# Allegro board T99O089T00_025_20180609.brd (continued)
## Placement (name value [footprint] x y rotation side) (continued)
C1405  22uF  [C-0805]  109.73 117.91 0 bottom
C1406  1UF  [S-C-0402]  118.36 129.72 270 bottom
C1407  0.1uF  [S-C-0402]  117.32 123.7 0 bottom
C1408  1UF  [S-C-0402]  111.25 118.17 180 bottom
C1409  0.1uF  [S-C-0402]  113.17 133.68 90 bottom
C1410  100nF  [C-0402S0]  29.47 45.23 90 bottom
C1411  1UF  [C-0402S0]  116.81 197.8 180 bottom
C1412  1UF  [C-0402S0]  75.82 122.34 270 bottom
C1413  1UF  [C-0402S0]  129.2 101.67 90 bottom
C1414  1nF  [C-0402S0]  118.59 186.62 0 top
C1415  1nF  [C-0402S0]  117.32 186.62 0 top
C1416  1nF  [C-0402S0]  116.05 186.62 0 top
C1417  1nF  [C-0402S0]  66.17 127.38 0 bottom
C1418  1nF  [C-0402S0]  114.78 186.62 0 top
C1419  1nF  [C-0402S0]  81.28 192.28 180 top
C1420  1nF  [C-0402S0]  110.33 194.24 270 top
C1421  1nF  [C-0402S0]  121.13 186.62 0 top
C1422  1nF  [C-0402S0]  119.86 186.62 0 top
C1548  1UF  [C-0402S0]  95 181.91 0 top
C1549  1uF  [C-0603S0]  261.97 188.4 270 top
C1550  22uF  [C-1210]  306.62 190.36 0 top
C1551  1uF  [C-0603S0]  260.91 189.11 0 bottom
C1552  1uF  [C-0603S0]  262.1 183.06 90 bottom
C1553  10uF  [C-0603S0]  286 190.68 0 bottom
C1554  100nF  [C-0402S0]  286.13 193.68 180 bottom
C1555  22nF  [C-0402S0]  259.02 190.09 270 bottom
C1556  1uF  [C-0603S0]  305.69 185.24 180 top
C1557  22uF  [C-1210]  57.12 163.66 0 top
C1558  100nF  [C-0402S0]  56.95 159.41 180 top
C1560  1uF  [C-0603S0]  276.84 188.92 90 bottom
C1561  1uF  [C-0603S0]  277.72 188.41 270 top
C1562  1uF  [C-0603S0]  277.85 183.08 90 bottom
C1563  1uF  [C-0603S0]  265.86 188.52 90 bottom
C1564  1uF  [C-0603S0]  266.8 188.52 270 top
C1565  1uF  [C-0603S0]  267.05 182.81 90 bottom
C1566  22nF  [C-0402S0]  276.68 190.14 90 bottom
C1567  22nF  [C-0402S0]  264.01 188.91 180 bottom
C1576  1uF  [C-0603S0]  285.16 186.1 90 bottom
C1577  1uF  [C-0603S0]  270.86 188.8 0 bottom
C1578  1uF  [C-0603S0]  269.09 185.04 180 top
C1579  1uF  [C-0603S0]  273.15 183.06 90 bottom
C1580  1uF  [C-0603S0]  280.25 186.31 0 bottom
C1581  1uF  [C-0603S0]  280.88 188.34 270 top
C1582  22nF  [C-0402S0]  269.47 189.08 0 bottom
C1583  22nF  [C-0402S0]  281.18 188.16 90 bottom
C1592  220pF  [C-0402S0]  43.43 200.28 180 top
C1593  220pF  [C-0402S0]  33.27 206.5 0 bottom
C1594  220pF  [C-0402S0]  36.96 197.74 90 bottom
C1595  10pF  [C-0402S0]  54.64 195.91 270 top
C1596  220pF  [C-0402S0]  45.95 191.57 0 bottom
C1597  220pF  [C-0402S0]  37.97 196.22 180 bottom
C1598  220pF  [C-0402S0]  43.43 196.09 180 top
C1599  220pF  [C-0402S0]  36.96 200.91 90 bottom
C1600  220pF  [C-0402S0]  37.08 204.98 180 bottom
C1601  10pF  [C-0402S0]  54.63 202.06 270 top
C1602  220pF  [C-0402S0]  45.59 191.9 0 top
C1603  220pF  [C-0402S0]  37.97 193.68 0 bottom
C1604  100nF  [C-0402S0]  69.34 178.69 0 bottom
C1622  27pF  [C-0402S0]  87.38 87.41 0 top
C1623  27pF  [C-0402S0]  87.38 89.49 180 top
C1624  47uF  [C-0805-H1_35]  100.2 86.83 0 bottom
C1625  1UF  [C-0402S0]  95.02 88.93 270 bottom
C1626  1UF  [C-0402S0]  94.55 92.31 270 bottom
C1627  1UF  [C-0402S0]  97.66 86.67 180 bottom
C1628  0.1uF  [C-0402S0]  92.76 94.4 90 bottom
C1629  0.1uF  [C-0402S0]  100.84 92.77 180 bottom
C1630  0.1uF  [C-0402S0]  98.68 86.67 0 bottom
C1631  0.1uF  [C-0402S0]  95.02 89.91 90 bottom
C1632  1uF  [C-0603S0]  101.6 84.01 90 top
C1633  1uF  [C-0603S0]  93.29 91.07 270 bottom
C1634  1uF  [C-0603S0]  97.43 93.26 180 bottom
C1635  0.1uF  [C-0402S0]  69.16 174.14 0 top
C1636  10uF  [C-0603S0]  4.47 103.33 180 top
C1637  39nF  [C-0402S0]  88.9 90.23 270 top
C1638  10uF  [C-0603S0]  95.38 86.54 0 bottom
C1639  1UF  [C-0402S0]  96.65 86.67 180 bottom
C1640  1UF  [C-0402S0]  92.38 87.61 270 bottom
C1641  100nF  [C-0402S0]  34.49 49.26 270 bottom
C1642  1UF  [C-0402S0]  93.85 86.03 180 bottom
C1643  10uF  [C-0603S0]  92.58 85.27 0 bottom
C1644  1UF  [C-0402S0]  125.38 118.53 180 top
C1672  1nF  [C-0402S0]  66.42 39.37 0 top
C1673  1nF  [C-0402S0]  80.79 43.88 180 bottom
C1674  1nF  [C-0402S0]  83.84 43.87 180 bottom
C1678  1UF  [C-0402S0]  47.35 89.48 90 bottom
C1679  100nF  [C-0402S0]  72.1 55.51 0 bottom
C1680  10pF  [C-0402S0]  62.73 41.33 0 top
C1681  10pF  [C-0402S0]  59.69 41.33 0 top
C1682  100nF  [C-0402S0]  71.63 52.7 90 bottom
C1683  100nF  [C-0402S0]  71.63 53.97 90 bottom
C1684  100nF  [C-0402S0]  76.45 52.33 90 bottom
C1685  150uF/ 3.22A  [CAH-R8-H6_9S0]  62.03 47.2 90 top
C1686  1UF  [C-0402S0]  56.86 45.44 180 bottom
C1687  1UF  [C-0402S0]  130.67 116.58 90 top
C1688  10uF  [C-0603S0]  126.92 116.27 0 top
C1689  1UF  [C-0402S0]  89.84 85.02 0 bottom
C1690  0.1uF  [C-0402S0]  134.81 121.33 270 top
C1815  1UF  [C-0402S0]  8.3 17.59 270 top
C1816  10uF  [C-0603S0]  5.44 102.36 180 bottom
C1817  1UF  [C-0402S0]  46.3 82.83 0 bottom
C1818  1UF  [C-0402S0]  73.81 63.07 0 bottom
C1935  1UF  [C-0402S0]  24.72 63.16 90 top
C1938  1UF  [C-0402S0]  20.82 20.23 270 top
C1940  1UF  [S-C-0402]  112.34 83.17 180 bottom
C1941  10uF  [S-C-0402]  113.38 83.19 0 bottom
C1942  1UF  [S-C-0402]  116.77 132.08 270 bottom
C1956  10uF  [C-0603S0]  8.3 27.13 90 bottom
C1978  0.1uF  [C-0402S0]  10.48 32.13 90 bottom
C1979  100nF  [C-0402S0]  35.43 46.34 270 bottom
C1980  100nF  [C-0402S0]  27.41 49.36 270 bottom
C1981  100nF  [C-0402S0]  50.42 66.04 0 top
C1982  10uF  [C-0603S0]  9.54 42.62 180 bottom
C1983  10uF  [C-0603S0]  13 42.62 0 bottom
C1985  0.1uF  [C-0402S0]  17.42 41.23 270 bottom
C1986  0.1uF  [C-0402S0]  17.42 39.96 270 bottom
C1987  0.1uF  [C-0402S0]  6.35 29.57 180 bottom
C1988  10uF  [C-0603S0]  8.3 29.98 270 bottom
C1989  1nF  [S-C-0402]  6.35 31.31 0 bottom
C1990  0ohm  [C-0402S0]  4.32 27.87 0 bottom
C1991  10uF  [C-0603S0]  74.67 77.48 0 bottom
C1992  0.1uF  [S-C-0402]  75.74 73.41 90 bottom
C1993  0.1uF  [S-C-0402]  80.31 80.39 180 bottom
C1994  0.1uF  [S-C-0402]  70.28 73.41 270 bottom
C1995  0.1uF  [S-C-0402]  72.06 73.41 270 bottom
C1996  10uF  [C-0603S0]  72.05 85.99 180 bottom
C1997  0.1uF  [S-C-0402]  73.39 86.17 180 bottom
C1998  0.1uF  [S-C-0402]  68.5 73.46 270 bottom
C1999  0.1uF  [S-C-0402]  73.36 77.3 0 bottom
C2000  0.1uF  [S-C-0402]  72.26 88.58 270 bottom
C2001  0.1uF  [S-C-0402]  80.37 83.21 0 bottom
C2002  0.1uF  [C-0402S0]  51.51 191.78 180 top
C2038  100nF  [C-0402S0]  142.26 130.82 0 top
C2039  10uF  [C-0603S0]  143.78 116.64 180 bottom
C2040  100nF  [C-0402S0]  138.22 122.48 90 bottom
C2041  100nF  [C-0402S0]  140.33 119.56 0 bottom
C2042  1UF  [C-0402S0]  11.18 77.47 270 top
C2043  10uF  [C-0603S0]  178.89 156.71 90 top
C2044  1UF  [C-0402S0]  179.17 155.49 270 top
C2045  100nF  [C-0402S0]  133.98 117.66 180 bottom
C2046  10uF  [C-0603S0]  134.62 120.71 90 bottom
C2047  100nF  [C-0402S0]  137.54 120.71 270 bottom
C2048  1UF  [C-0402S0]  150.06 141.73 90 top
C2049  10uF  [C-0603S0]  187.63 156.89 90 bottom
C2050  1UF  [C-0402S0]  187.32 155.61 270 bottom
C2051  1UF  [C-0402S0]  160.78 83.47 180 top
C2052  10uF  [C-0603S0]  163.83 83.22 180 top
C2053  1UF  [C-0402S0]  165.1 83.42 0 top
C2054  1UF  [C-0402S0]  152.49 113.67 180 top
C2055  10uF  [C-0603S0]  155.2 113.82 180 top
C2056  1UF  [C-0402S0]  156.51 113.92 0 top
C2057  1UF  [C-0402S0]  168.16 97.72 0 top
C2058  10uF  [C-0603S0]  165.24 97.59 0 top
C2059  1UF  [C-0402S0]  163.97 97.46 180 top
C2060  10uF  [C-1206]  303.28 190.57 0 top
C2061  100nF  [C-0402S0]  92.48 194.78 270 bottom
C2062  100nF  [C-0402S0]  67.82 183.9 0 bottom
C2063  0.1uF  [S-C-0402]  90.04 167.26 180 bottom
C2064  0.1uF  [S-C-0402]  91.06 167.26 180 bottom
C2065  0.1uF  [S-C-0402]  93.22 167.26 180 bottom
C2066  0.1uF  [S-C-0402]  94.23 167.26 180 bottom
C2067  0.1uF  [S-C-0402]  107.54 167.24 180 bottom
C2068  0.1uF  [S-C-0402]  108.56 167.24 180 bottom
C2069  0.1uF  [S-C-0402]  119.13 147.96 0 bottom
C2070  0.1uF  [S-C-0402]  118.11 147.96 0 bottom
C2071  0.1uF  [S-C-0402]  124.43 148.01 0 bottom
C2072  0.1uF  [S-C-0402]  125.57 148.01 0 bottom
C2073  0.1uF  [S-C-0402]  128.02 148.01 0 bottom
C2074  0.1uF  [S-C-0402]  127 148.01 0 bottom
C2076  1UF  [C-0402S0]  57.36 52.43 270 bottom
C2077  0.1uF  [S-C-0402]  276.6 94.39 180 bottom
C2078  22uF  [C-0805]  25.52 104.09 0 top
C2079  10uF  [C-0603S0]  23.75 104.01 0 top
C2080  1nF  [S-C-0402]  20.43 91.8 90 bottom
C2081  0.1uF  [S-C-0402]  19.93 90.3 0 bottom
C2082  0.1uF  [S-C-0402]  22.93 94.3 0 bottom
C2083  0.1uF  [S-C-0402]  191.99 130.58 0 bottom
C2084  22uF  [C-0805]  4.9 86.38 270 top
C2085  10uF  [C-0603S0]  5.03 88.29 270 top
C2086  1nF  [S-C-0402]  14.43 87.81 90 bottom
C2087  0.1uF  [S-C-0402]  14.43 88.79 270 bottom
C2088  0.1uF  [S-C-0402]  17.43 86.8 270 bottom
C2089  10uF  [C-0603S0]  31.05 103.03 270 bottom
C2090  47uF  [C-1206]  10.84 103.4 0 top
C2091  10uF  [C-0603S0]  13.13 103.35 0 top
C2092  1nF  [S-C-0402]  21.43 95.8 90 bottom
C2093  0.1uF  [S-C-0402]  14.43 91.8 270 bottom
C2094  0.1uF  [S-C-0402]  14.43 90.8 90 bottom
C2095  0.1uF  [S-C-0402]  21.43 94.8 270 bottom
C2096  0.1uF  [S-C-0402]  21.43 93.8 270 bottom
C2097  10uF  [C-0603S0]  88.27 81.34 180 bottom
C2098  47uF  [C-1206]  13.56 102.7 180 bottom
C2099  10uF  [C-0603S0]  15.62 102.37 180 bottom
C2100  0.1uF  [S-C-0402]  15.93 97.3 0 bottom
C2101  1nF  [S-C-0402]  15.43 98.8 90 bottom
C2102  0.1uF  [S-C-0402]  14.43 97.8 270 bottom
C2103  0.1uF  [S-C-0402]  22.93 97.3 0 bottom
C2104  0.1uF  [S-C-0402]  21.93 97.3 0 bottom
C2105  10uF  [C-0603S0]  75.46 47.45 180 top
C2106  47uF  [C-1206]  29.04 99.63 180 bottom
C2107  10uF  [C-0603S0]  27.11 99.68 180 bottom
C2108  0.1uF  [S-C-0402]  17.93 96.3 0 bottom
C2109  1nF  [S-C-0402]  20.93 97.3 0 bottom
C2110  0.1uF  [S-C-0402]  20.93 90.3 180 bottom
C2111  0.1uF  [S-C-0402]  22.43 91.8 270 bottom
C2112  0.1uF  [S-C-0402]  23.93 94.3 180 bottom
C2113  10uF  [C-0603S0]  101.6 82.61 270 top
C2114  47uF  [C-1206]  5.52 92.31 90 top
C2115  10uF  [C-0603S0]  5.33 90.38 90 top
C2116  0.1uF  [S-C-0402]  24.43 91.8 270 bottom
C2117  1nF  [S-C-0402]  13.43 95.8 90 bottom
C2118  0.1uF  [S-C-0402]  24.93 94.3 0 bottom
C2119  0.1uF  [S-C-0402]  24.93 97.3 180 bottom
C2120  0.1uF  [S-C-0402]  15.43 95.8 90 bottom
C2121  0.1uF  [C-0402S0]  101.22 90.99 0 bottom
C2122  100nF  [C-0402S0]  68.2 177.93 0 bottom
C2123  100nF  [C-0402S0]  93.98 178.87 270 top
C2124  100nF  [C-0402S0]  116.05 115.28 0 bottom
C2125  10uF  [S-C-0402]  37.9 56.81 0 top
C2127  10uF  [C-0603S0]  27.05 89.21 90 bottom
C2128  0.1uF  [S-C-0402]  24.43 89.8 270 bottom
C2129  0.1uF  [S-C-0402]  22.43 89.8 270 bottom
C2130  10uF  [C-0603S0]  27.91 90.59 90 bottom
C2131  0.1uF  [S-C-0402]  22.43 90.8 270 bottom
C2132  1UF  [C-0402S0]  162.3 133.79 0 bottom
C2133  10uF  [C-0603S0]  14.71 138.96 0 bottom
C2134  47uF  [C-1206]  25.5 140.04 180 bottom
C2135  10uF  [C-0603S0]  27.43 140.84 180 bottom
C2136  0.1uF  [C-0402S0]  29.66 140.66 180 bottom
C2137  1nF  [C-0402S0]  28.65 140.66 0 bottom
C2138  100uF  [C-1210]  22.26 140.1 180 bottom
C2139  1UF  [S-C-0402]  16.93 96.3 180 bottom
C2140  10uF  [C-0603S0]  161.35 125.11 0 bottom
C2141  1UF  [C-0402S0]  156.72 127.31 90 bottom
C2142  1UF  [C-0402S0]  166.24 125.15 0 bottom
C2143  1UF  [C-0402S0]  160.15 127.56 180 bottom
C2144  1UF  [C-0402S0]  159.13 133.03 180 bottom
C2145  1UF  [C-0402S0]  160.03 131.42 90 bottom
C2146  10uF  [C-0603S0]  162.71 136.05 90 bottom
C2147  1UF  [C-0402S0]  160.15 133.03 0 bottom
C2148  1UF  [C-0402S0]  156.46 133.53 180 bottom
C2149  1UF  [C-0402S0]  158.49 127.04 90 bottom
C2150  1UF  [C-0402S0]  154.91 133.36 180 bottom
C2151  1UF  [C-0402S0]  153.14 129.34 270 bottom
C2152  1UF  [C-0402S0]  154.03 128.15 270 bottom
C2153  10uF  [C-0603S0]  150.39 137.03 90 top
C2154  1UF  [C-0402S0]  180.59 158.3 0 top
C2155  1UF  [C-0402S0]  159.71 130.17 90 bottom
C2156  10uF  [C-0603S0]  163.18 129.34 90 bottom
C2157  1UF  [C-0402S0]  185.68 156.6 180 bottom
C2158  0.1uF  [C-0402S0]  147.68 135.57 270 top
C2159  0.1uF  [C-0402S0]  147.65 134.56 270 top
C2160  100nF  [C-0402S0]  72.39 94.36 90 bottom
C2161  100nF  [C-0402S0]  39.34 189.24 270 bottom
C2162  100nF  [C-0402S0]  25.86 124.92 90 top
C2163  0.1uF  [C-0402S0]  164.57 132.14 270 top
C2164  0.1uF  [C-0402S0]  164.57 131.12 270 top
C2165  0.1uF  [C-0402S0]  164.57 129.09 270 top
C2166  0.1uF  [C-0402S0]  164.57 128.07 270 top
C2167  0.1uF  [C-0402S0]  161.08 122.87 270 top
C2168  0.1uF  [C-0402S0]  161.08 121.85 270 top
C2169  0.1uF  [C-0402S0]  49.86 113.31 90 bottom
C2170  0.1uF  [C-0402S0]  49.86 109.47 90 bottom
C2171  1UF  [C-0402S0]  165.11 140.23 0 bottom
C2172  1UF  [S-C-0402]  24.43 95.8 90 bottom
C2173  22uF  [C-0805]  163.14 125 0 bottom
C2174  22uF  [C-0805]  162.81 137.76 90 bottom
C2175  22uF  [C-0805]  151.38 139.57 0 top
C2176  150uF/ 3.22A  [CAH-R8-H6_9S0]  38.97 185.6 90 top
C2204  0.1uF  [C-0402S0]  296.85 91.75 90 top
C2205  0.1uF  [C-0402S0]  296.85 92.76 90 top
C2206  100nF  [C-0402S0]  105.05 77.7 270 bottom
C2207  10uF  [C-0603S0]  104.78 82.1 270 bottom
C2208  100nF  [C-0402S0]  106.63 82.94 180 bottom
C2209  100nF  [C-0402S0]  97.16 178.87 270 top
C2210  10uF  [C-0603S0]  92.21 191.87 90 bottom
C2211  100nF  [C-0402S0]  90.23 192.28 180 bottom
C2215  100nF  [C-0402S0]  136.86 201.11 90 top
C2216  100nF  [C-0402S0]  153.48 76.53 0 top
C2217  100nF  [C-0402S0]  141.4 76.53 0 top
C2218  1nF  [C-0402S0]  118.87 192.3 0 bottom
C2219  100nF  [S-C-0402]  274.14 11.18 270 bottom
C2220  0.1uF  [C-0402S0]  84.85 43.87 180 bottom
C2221  100nF  [S-C-0402]  217.68 27.76 90 bottom
C2224  1UF  [C-0402S0]  78.5 173.53 270 top
C2229  1UF  [C-0402S0]  73.84 65.72 270 top
C2235  0.1uF  [C-0402S0]  185.67 146.31 180 top
C2236  0.1uF  [C-0402S0]  186.69 146.31 180 top
C2237  0.1uF  [C-0402S0]  188.72 151.69 270 top
C2238  0.1uF  [C-0402S0]  188.72 152.71 270 top
C2239  0.1uF  [C-0402S0]  190.3 120.65 90 top
C2240  0.1uF  [C-0402S0]  43.06 113.46 0 bottom
C2241  0.1uF  [C-0402S0]  38.33 116.53 0 bottom
C2242  0.1uF  [C-0402S0]  67.92 100.2 0 top
C2243  0.1uF  [C-0402S0]  68.94 100.2 0 top
C2244  0.1uF  [C-0402S0]  49.86 110.44 270 bottom
C2245  22uF  [C-0805]  57.87 141.6 270 top
C2246  0.1uF  [S-C-0402]  59.67 114.75 90 bottom
C2247  0.1uF  [S-C-0402]  59.67 113.74 90 bottom
C2248  0.1uF  [S-C-0402]  45.44 116.02 90 bottom
C2249  0.1uF  [S-C-0402]  45.44 123.26 90 bottom
C2250  1nF  [S-C-0402]  38.71 114.5 90 bottom
C2251  0.1uF  [S-C-0402]  59.78 110.43 90 bottom
C2252  1uF  [S-C-0402]  38.33 120.6 180 bottom
C2253  1uF  [S-C-0402]  38.33 122.37 180 bottom
C2254  1uF  [S-C-0402]  38.33 118.82 0 bottom
C2255  22uF  [C-0805]  57.87 139.57 270 top
C2256  0.1uF  [S-C-0402]  40.99 120.85 90 bottom
C2257  0.1uF  [S-C-0402]  46.21 110.56 0 bottom
C2258  0.1uF  [S-C-0402]  46.21 112.47 0 bottom
C2259  0.1uF  [S-C-0402]  46.94 119.2 90 bottom
C2260  1nF  [S-C-0402]  59.78 109.49 270 bottom
C2261  0.1uF  [S-C-0402]  40.97 121.86 90 bottom
C2262  1uF  [S-C-0402]  46.97 120.21 270 bottom
C2263  1uF  [S-C-0402]  46.21 121.61 0 bottom
C2264  1uF  [S-C-0402]  46.46 117.67 0 bottom
C2266  1UF  [S-C-0402]  56.77 93.94 0 top
C2267  10uF  [S-C-0402]  55.83 93.94 180 top
C2268  1UF  [S-C-0402]  59.66 92.99 90 top
C2269  0.1uF  [S-C-0402]  54.16 105.9 0 bottom
C2270  10uF  [C-0603S0]  52.81 105.61 0 bottom
C2271  0.1uF  [S-C-0402]  67.67 116.91 270 bottom
C2272  1UF  [C-0402S0]  51.94 83.95 270 bottom
C2273  1UF  [C-0402S0]  32.13 80.69 0 top
C2274  1UF  [C-0402S0]  93.85 140.9 0 top
C2275  0.1uF  [S-C-0402]  65.64 109.42 180 bottom
C2276  10uF  [C-0603S0]  57.89 127.33 270 bottom
C2277  1UF  [S-C-0402]  58.14 126.06 90 bottom
C2278  0.1uF  [S-C-0402]  58.14 125.04 270 bottom
C2279  0.1uF  [S-C-0402]  63.61 109.42 180 bottom
C2280  10uF  [C-0603S0]  60.56 127.33 90 bottom
C2281  1UF  [S-C-0402]  60.3 126.06 270 bottom
C2282  0.1uF  [S-C-0402]  60.3 125.04 90 bottom
C2283  0.1uF  [S-C-0402]  66.13 127.76 180 top
C2284  0.1uF  [S-C-0402]  66.55 126.17 90 top
C2285  0.1uF  [S-C-0402]  61.57 109.42 180 bottom
C2286  1nF  [S-C-0402]  67.03 109.59 90 bottom
C2287  1UF  [S-C-0402]  60.74 116.66 180 bottom
C2288  22uF  [C-0805]  73.89 143.84 270 top
C2289  0.1uF  [S-C-0402]  62.59 109.42 180 bottom
C2290  1UF  [S-C-0402]  49.89 107.13 0 top
C2291  0.1uF  [S-C-0402]  50.91 107.13 180 top
C2292  0.1uF  [S-C-0402]  67.18 127.76 180 top
C2293  1uF  [S-C-0402]  67.03 110.56 90 bottom
C2294  0.1uF  [S-C-0402]  37.06 107.51 0 bottom
C2295  0.1uF  [S-C-0402]  59.8 116.66 0 bottom
C2296  0.1uF  [S-C-0402]  64.62 109.42 180 bottom
C2297  10uF  [C-0603S0]  48.62 106.88 180 top
C2298  0.1uF  [S-C-0402]  60.43 129.99 270 bottom
C2299  10uF  [C-0603S0]  44.05 102.56 180 bottom
C2300  1UF  [S-C-0402]  45.32 102.69 0 bottom
C2301  0.1uF  [S-C-0402]  46.86 102.23 90 bottom
C2302  22uF  [C-0805]  57.87 142.11 90 bottom
C2303  0.1uF  [S-C-0402]  38.33 111.32 180 bottom
C2304  0.1uF  [S-C-0402]  38.33 113.1 180 bottom
C2305  0.1uF  [S-C-0402]  39.98 116.15 90 bottom
C2306  1nF  [S-C-0402]  43.16 117.8 180 bottom
C2307  0.1uF  [S-C-0402]  36.94 104.47 180 bottom
C2308  10uF  [C-0603S0]  39.86 107.51 180 bottom
C2309  1UF  [S-C-0402]  41.13 107.51 0 bottom
C2310  0.1uF  [S-C-0402]  42.14 107.51 180 bottom
C2311  22uF  [C-0805]  66.35 113.23 270 bottom
C2312  0.1uF  [S-C-0402]  58.53 117.42 180 bottom
C2313  0.1uF  [S-C-0402]  57.89 129.99 90 bottom
C2314  0.1uF  [S-C-0402]  41.25 102.82 0 bottom
C2315  1nF  [S-C-0402]  66.91 114.75 90 bottom
C2316  0.1uF  [S-C-0402]  45.83 106.63 0 top
C2317  1UF  [S-C-0402]  66.27 116.66 180 bottom
C2318  1UF  [S-C-0402]  67.03 111.71 90 bottom
C2319  0.1uF  [S-C-0402]  50.02 105.61 180 bottom
C2320  1UF  [S-C-0402]  61.7 116.66 180 bottom
C2321  0.1uF  [S-C-0402]  63.35 117.1 270 bottom
C2322  10uF  [C-0603S0]  39.73 104.59 0 bottom
C2323  1UF  [S-C-0402]  41.25 104.85 180 bottom
C2324  0.1uF  [S-C-0402]  42.27 104.85 0 bottom
C2325  100nF  [S-C-0402]  44.59 129.63 180 top
C2326  22pF  [C-0402S0]  141.22 195.33 270 top
C2327  1nF  [C-0402S0]  51.59 129.36 270 top
C2330  1uF  [C-0603S0]  59.6 198.03 90 top
C2331  1uF  [C-0603S0]  67.93 138.9 90 bottom
C2332  1uF  [C-0603S0]  83.29 139.51 270 top
C2333  10uF  [C-0603S0]  5.59 98.66 270 top
C2334  1UF  [C-0402S0]  57.97 82.4 180 bottom
C2335  10uF  [C-0603S0]  86.49 83.19 270 bottom
C2338  0.1uF  [C-0402S0]  173.98 84.52 270 top
C2339  0.1uF  [C-0402S0]  173.98 85.54 270 top
C2340  0.1uF  [C-0402S0]  173.98 86.81 270 top
C2341  0.1uF  [C-0402S0]  173.98 87.77 270 top
C2342  0.1uF  [C-0402S0]  188.57 117.95 270 top
C2343  0.1uF  [C-0402S0]  188.56 118.92 270 top
C2344  0.1uF  [C-0402S0]  166.12 92.91 0 top
C2345  0.1uF  [C-0402S0]  167.11 92.91 0 top
C2346  0.1uF  [C-0402S0]  183.13 146.31 180 top
C2347  0.1uF  [C-0402S0]  184.14 146.31 180 top
C2348  100nF  [C-0402S0]  140.17 123 180 bottom
C2350  100nF  [C-0402S0]  141.49 122.22 90 bottom
C2352  100nF  [C-0402S0]  141.1 120.83 90 bottom
C2356  100nF  [C-0402S0]  146.57 116.52 0 bottom
C2357  100nF  [C-0402S0]  138.25 130.56 180 top
C2358  10uF  [C-0603S0]  139.57 130.74 180 top
C2359  1UF  [C-0402S0]  44.32 68.71 90 bottom
C2360  1UF  [C-0402S0]  74.22 47.6 0 top
C2361  1UF  [C-0402S0]  82.49 173.58 90 top
C2362  0.1uF  [C-0402S0]  9.86 79.38 0 top
C2363  0.1uF  [C-0402S0]  8.84 79.38 0 top
C2364  0.1uF  [C-0402S0]  154.76 137.55 180 top
C2365  0.1uF  [C-0402S0]  153.7 137.55 180 top
C2366  0.1uF  [C-0402S0]  149.1 126.17 270 top
C2367  0.1uF  [C-0402S0]  149.1 125.15 270 top
C2368  100nF  [C-0402S0]  102.31 179.37 90 top
C2369  100nF  [C-0402S0]  107.46 89.43 270 bottom
C2370  0.1uF  [C-0402S0]  95.5 98.3 180 top
C2371  0.1uF  [C-0402S0]  96.49 98.3 180 top
C2372  100nF  [C-0402S0]  139.54 194.75 180 top
C2373  1UF  [C-0402S0]  80.57 55.15 0 top
C2374  1UF  [C-0402S0]  63.83 132.59 180 top
C2375  0.1uF  [S-C-0402]  58.41 108.44 180 bottom
C2376  100nF  [C-0402S0]  73.64 140.74 270 top
C2377  100nF  [C-0402S0]  62.9 123.31 0 bottom
C2378  100nF  [C-0402S0]  60.81 125.8 270 top
C2381  680pF  [C-0402S0]  13.38 79.38 0 top
C2382  680pF  [C-0402S0]  12.36 79.38 0 top
C2383  0.1uF  [C-0402S0]  176.78 153.73 270 top
C2384  0.1uF  [C-0402S0]  176.78 152.71 270 top
C2385  0.1uF  [C-0402S0]  37.88 54.11 0 top
C2386  1UF  [S-C-0402]  121.84 96.32 90 bottom
C2387  1uF  [S-C-0402]  184.39 141.44 90 top
C2388  10uF  [S-C-0402]  192.49 139.13 0 top
C2389  0.1uF  [S-C-0402]  237.07 120.92 0 bottom
C2390  1uF  [S-C-0402]  121.84 99.3 90 bottom
C2392  0.1uF  [C-0402S0]  36.91 56.79 180 top
C2393  10pF  [C-0402S0]  29.44 80.52 0 top
C2394  10pF  [C-0402S0]  22.69 76.23 270 top
C2397  100nF  [C-0402S0]  128.52 201.17 270 top
C2398  10nF  [C-0402S0]  28.8 18.13 90 top
C2399  100nF  [C-0402S0]  125.46 76.28 0 top
C2400  100nF  [C-0402S0]  159.97 86.09 270 top
C2401  1UF  [C-0402S0]  88.01 79.18 270 bottom
C2402  100nF  [C-0402S0]  141.11 201.11 90 top
C2403  1UF  [C-0402S0]  89.41 133.35 270 top
C2404  1UF  [C-0402S0]  87.38 129.51 0 top
C2406  100pF  [S-C-0402]  223.27 173.54 0 bottom
C2407  0.1uF  [C-0402S0]  18.92 79.43 0 top
C2408  0.1uF  [C-0402S0]  19.94 79.43 0 top
C2409  0.1uF  [S-C-0402]  24.62 67.77 0 top
C2410  0.1uF  [S-C-0402]  35.7 51.81 180 top
C2411  1nF  [C-1808]  50.85 47.4 0 bottom
C2412  1nF  [C-0805-H0_95]  50.85 60.28 180 bottom
C2413  1nF  [C-1808]  44.5 47.4 180 bottom
C2414  1nF  [C-0805-H0_95]  44.5 60.28 180 bottom
C2415  0.1uF  [C-0402S0]  148.21 90.89 90 bottom
C2416  10uF  [S-C-0402]  148.21 89.87 270 bottom
C2417  0.1uF  [C-0402S0]  145.82 85.65 90 bottom
C2420  0.1uF  [C-0402S0]  145.92 84.52 90 bottom
C2421  10uF  [S-C-0402]  145.92 83.4 270 bottom
C2422  0.1uF  [C-0402S0]  148.21 91.9 90 bottom
C2423  100nF  [C-0402S0]  28.33 12.52 270 top
C2424  10nF  [C-0402S0]  15.75 16.41 90 top
C2425  10nF  [C-0402S0]  14.62 21.93 180 top
C2426  1UF  [C-0402S0]  81.2 123.38 180 top
C2427  100pF  [C-0402S0]  11.68 17.88 180 bottom
C2428  100pF  [C-0402S0]  11.51 21.93 0 top
C2429  100pF  [C-0402S0]  13.61 21.93 180 top
C2430  0.1uF  [C-0402S0]  22.8 12.92 180 top
C2431  100nF  [C-0402S0]  132.97 172.97 0 top
C2432  1UF  [C-0402S0]  119.89 178.82 180 top
C2433  1UF  [C-0402S0]  85.16 173.46 90 top
C2434  1nF  [C-0402S0]  63.88 131.06 270 bottom
C2435  1nF  [C-0402S0]  64.39 128.02 90 top
C2436  100nF  [C-0402S0]  274.87 116.63 90 top
C2437  1UF  [C-0402S0]  88.77 140.9 0 top
C2439  1UF  [C-0402S0]  222.76 176.12 270 top
C2440  4.7uF  [C-0603S0]  115.24 202.77 270 top
C2441  100nF  [C-0402S0]  115.52 201.47 90 top
C2442  10nF  [C-0402S0]  115.82 197.8 180 bottom
C2443  1nF  [C-0402S0]  121.51 183.95 0 bottom
C2446  0.1uF  [C-0402S0]  52.45 197.28 90 top
C2447  0.1uF  [C-0402S0]  48.87 187.3 270 top
C2448  100nF  [C-0402S0]  132.51 190.79 0 top
C2449  100nF  [C-0402S0]  85.34 111.46 90 top
C2450  100nF  [C-0402S0]  64.84 116.38 90 bottom
C2451  100nF  [C-0402S0]  285.96 98.65 90 bottom
C2452  1nF  [C-0402S0]  137.31 199.31 180 bottom
C2453  0.1uF  [C-0402S0]  62.23 179.32 0 top
C2454  22pF  [C-0402S0]  66.12 179.57 180 top
C2461  1UF  [C-0402S0]  87.29 122.93 90 top
C2462  0.1uF  [S-C-0402]  108.68 138.78 90 bottom
C2463  100nF  [C-0402S0]  194.69 123.26 270 bottom
CJ8  UE86-K8627-20321  [SFP-2X8-389]  141.13 28.23 0 top
CJ9  UE86-3G6620-20361  [SFP-2X6-240E-TEMP]  244.43 28.22 0 top
CJ12  171722-6001  [SFP-2X1-76B]  301.56 33.19 0 top
CN1  HS1105H-RN  [S-CN-S5X2-2_54S0]  122.9 145.8 270 top
CN3  46437-1044  [CN-D33_01X32-45SK-TEMP]  20.01 203.98 180 top
CN6  HS1105H-RN  [S-CN-S5X2-2_54S0]  108.58 102.42 270 top
D1  LTST-C295KGKSKT-F  [LD-S1_6X0_8-4A]  85.14 54.23 180 top
D2  LTST-C295KGKSKT-F  [LD-S1_6X0_8-4A]  97.37 54.13 180 top
D3  LTST-C295KGKSKT-F  [LD-S1_6X0_8-4A]  99.36 54.1 180 top
D4  LTST-C295KGKSKT-F  [LD-S1_6X0_8-4A]  111.62 54.13 180 top
D5  LTST-C295KGKSKT-F  [LD-S1_6X0_8-4A]  113.61 54.1 180 top
D6  LTST-C295KGKSKT-F  [LD-S1_6X0_8-4A]  125.87 54.13 180 top
D7  LTST-C295KGKSKT-F  [LD-S1_6X0_8-4A]  127.88 54.13 180 top
D8  LTST-C295KGKSKT-F  [LD-S1_6X0_8-4A]  140.12 54.13 180 top
D9  LTST-C295KGKSKT-F  [LD-S1_6X0_8-4A]  142.13 54.13 180 top
D10  LTST-C295KGKSKT-F  [LD-S1_6X0_8-4A]  154.37 54.13 180 top
D11  LTST-C295KGKSKT-F  [LD-S1_6X0_8-4A]  156.38 54.13 180 top
D12  LTST-C295KGKSKT-F  [LD-S1_6X0_8-4A]  168.62 54.13 180 top
D13  LTST-C295KGKSKT-F  [LD-S1_6X0_8-4A]  170.63 54.13 180 top
D14  LTST-C295KGKSKT-F  [LD-S1_6X0_8-4A]  182.87 54.13 180 top
D15  LTST-C295KGKSKT-F  [LD-S1_6X0_8-4A]  184.88 54.13 180 top
D16  LTST-C295KGKSKT-F  [LD-S1_6X0_8-4A]  197.12 54.13 180 top
D17  LTST-C295KGKSKT-F  [LD-S1_6X0_8-4A]  260.4 49.39 180 top
D18  LTST-C295KGKSKT-F  [LD-S1_6X0_8-4A]  271.2 49.39 180 top
D19  LTST-C295KGKSKT-F  [LD-S1_6X0_8-4A]  274.65 49.39 180 top
D20  LTST-C295KGKSKT-F  [LD-S1_6X0_8-4A]  285.45 49.39 180 top
D25  LTST-C295KGKSKT-F  [LD-S1_6X0_8-4A]  107.06 137.67 0 top
D26  LTST-C295KGKSKT-F  [LD-S1_6X0_8-4A]  81.72 129.9 270 top
D33  LTST-C295KGKSKT-F  [LD-S1_6X0_8-4A]  203.4 49.39 180 top
D34  LTST-C295KGKSKT-F  [LD-S1_6X0_8-4A]  214.2 49.39 180 top
D35  LTST-C295KGKSKT-F  [LD-S1_6X0_8-4A]  217.65 49.39 180 top
D36  LTST-C295KGKSKT-F  [LD-S1_6X0_8-4A]  228.45 49.39 180 top
D37  LTST-C295KGKSKT-F  [LD-S1_6X0_8-4A]  231.9 49.39 180 top
D38  LTST-C295KGKSKT-F  [LD-S1_6X0_8-4A]  242.7 49.39 180 top
D39  LTST-C295KGKSKT-F  [LD-S1_6X0_8-4A]  246.15 49.39 180 top
D40  LTST-C295KGKSKT-F  [LD-S1_6X0_8-4A]  256.95 49.39 180 top
D41  LTST-C295KGKSKT-F  [LD-S1_6X0_8-4A]  293.05 49.51 0 top
D42  LTST-C295KGKSKT-F  [LD-S1_6X0_8-4A]  294.06 13.11 0 bottom
D43  SP4020-01FTG  [SOD-323H1_1]  111.6 196.14 90 top
D44  SP4020-01FTG  [SOD-323H1_1]  41.78 192.66 0 top
D45  SP4020-01FTG  [SOD-323H1_1]  42.29 194.69 90 bottom
D46  SP4020-01FTG  [SOD-323H1_1]  33.78 192.91 0 bottom
D47  SP4020-01FTG  [SOD-323H1_1]  33.78 196.98 180 bottom
D48  SP4020-01FTG  [SOD-323H1_1]  41.78 196.85 0 top
D49  SP4020-01FTG  [SOD-323H1_1]  41.78 201.04 0 top
D50  SP4020-01FTG  [SOD-323H1_1]  35.31 193.47 270 top
D51  SP4020-01FTG  [SOD-323H1_1]  35.31 191.44 270 top
D52  SP4020-01FTG  [SOD-323H1_1]  35.43 205.74 180 bottom
D53  SP4020-01FTG  [SOD-323H1_1]  37.72 202.69 90 bottom
D54  SP4020-01FTG  [SOD-323H1_1]  37.72 199.26 90 bottom
D55  SP4020-01FTG  [SOD-323H1_1]  31.5 205.74 0 bottom
D59  RClamp3374N.TCT  [EQFN-3X2-10SS0]  74.55 40.26 90 top
D60  RClamp3374N.TCT  [EQFN-3X2-10SS0]  79.12 40.26 90 top
D61  AZ1355-04S.R7G  [SOT-23-6H1_25]  69.85 39.96 0 top
D63  SMBJ6.0CA  [D-SMBS0]  7.62 22.08 90 bottom
D65  AZ1355-04S.R7G  [SOT-23-6H1_25]  37.52 15.94 90 top
D67  AZ1355-04S.R7G  [SOT-23-6H1_25]  9.49 14.54 180 top
D68  AZ1355-04S.R7G  [SOT-23-6H1_25]  30.79 66.97 180 top
D69  AZ1355-04S.R7G  [SOT-23-6H1_25]  16.95 67.55 180 top
D73  P0080SALRP  [DO-214A-H2_65]  24.26 27.36 180 top
D74  P0080SALRP  [DO-214A-H2_65]  29.03 27.36 180 top
D75  P0080SALRP  [DO-214A-H2_65]  33.81 27.36 180 top
D76  P0080SALRP  [DO-214A-H2_65]  38.58 27.36 180 top
D77  P0080SALRP  [DO-214A-H2_65]  63.53 69.27 90 top
D80  P0080SALRP  [DO-214A-H2_65]  56.98 71.06 180 top
D85  LTST-C295KGKSKT-F  [LD-S1_6X0_8-4A]  293.05 59.72 0 top
D86  LTST-C295KGKSKT-F  [LD-S1_6X0_8-4A]  296.75 13.11 0 bottom
D87  LTST-C295KGKSKT-F  [LD-S1_6X0_8-4A]  310.04 59.72 0 top
D88  LTST-C295KGKSKT-F  [LD-S1_6X0_8-4A]  306.36 13.11 0 bottom
D89  LTST-C295KGKSKT-F  [LD-S1_6X0_8-4A]  310.04 49.51 0 top
D90  LTST-C295KGKSKT-F  [LD-S1_6X0_8-4A]  309.05 13.11 0 bottom
D92  RClamp3374N.TCT  [EQFN-3X2-10SS0]  30.5 33.82 270 top
D93  RClamp3374N.TCT  [EQFN-3X2-10SS0]  47.69 62.59 270 top
D97  L35L12VCB2  [SOD-323C]  59.94 38.54 180 top
D98  L35L12VCB2  [SOD-323C]  62.1 38.54 180 top
D99  BS0640N-C-F  [F-S5_4X3_3-2]  45.72 38.21 180 top
D100  BS0640N-C-F  [F-S5_4X3_3-2]  41.53 38.21 0 top
D101  BS0640N-C-F  [F-S5_4X3_3-2]  45.6 39.21 180 bottom
D102  BS0640N-C-F  [F-S5_4X3_3-2]  50.05 39.21 180 bottom
D103  BS0640N-C-F  [F-S5_4X3_3-2]  49.91 38.21 0 top
D104  BS0640N-C-F  [F-S5_4X3_3-2]  54.1 38.21 180 top
F1  0467.500NRHF  [R-0603S0]  58.13 35.07 270 top
F2  0467.500NRHF  [R-0603S0]  58.13 33.68 270 top
F3  0467.500NRHF  [R-0603S0]  41.87 32.42 180 top
F4  0467.500NRHF  [R-0603S0]  40.43 32.42 180 top
H1  Hole-3.5mm  [GMTH138R394KO472]  98.3 112.39 0 top
H2  Hole-3.5mm  [GMTH138R394KO472]  25.61 188.69 0 top
H3  Hole-3.5mm  [GMTH138R394KO472]  7.62 59.49 0 top
H4  Hole-4.6mm  [GMTH181R325S0]  306.95 209.86 0 top
H5  Hole-3.5mm  [GMTH138R394KO472]  304.92 121.2 0 top
H6  Hole-3.5mm  [GMTH138R394KO472]  175.92 209.86 0 top
H7  Hole-3.5mm  [GMTH138R394KO472]  161.7 165.6 0 top
H8  Hole-3.5mm  [GMTH138R394KO472]  196.92 70.69 0 top
H9  Hole-3.5mm  [GMTH138R394KO472]  253.7 177.55 0 top
H10  Hole-3.5mm  [GMTH138R394KO472]  64.26 59.49 0 top
H11  Hole-3.5mm  [GMTH138R394KO472]  53.7 177.55 0 top
H12  Hole-3.5  [GMTH138R315A]  44.84 209.83 0 top
H13  Hole-3.5  [GMTH138R315A]  282.55 66.62 0 top
H14  Hole-3.5  [MPTH138R197]  176.79 94.42 0 top
H15  Hole-3.5  [MPTH138R197]  251.87 94.42 0 top
H16  Hole-3.5  [MPTH138R197]  251.87 145.57 0 top
H17  Hole-3.5  [MPTH138R197]  176.79 145.57 0 top
H18  Hole-3.1  [MPTH122R177]  264.1 80.92 0 top
H19  Hole-3.1  [MPTH122R177]  304.1 103.92 0 top
H20  Hole-4.6mm  [GMTH181R325S0]  6.73 144.91 0 top
H21  Hole-1.2X2.2  [MPTH47X87R71X111]  31.24 109.23 270 top
H22  Hole-1.2X2.2  [MPTH47X87R71X111]  5.54 135.33 270 top
H23  Hole-1.2X2.2  [MPTH47X87R71X111]  31.24 135.33 270 top
H24  Hole-1.2X2.2  [MPTH47X87R71X111]  5.54 109.23 270 top
J1  98317C-164-2MMF  [CN-EXPPCI-164A]  105.54 160.93 180 top
J3  20438-04321  [CN-S10_16X5_1-4]  140.66 139.29 270 top
J5  HS5513V-R  [CN-S13X2-2HD]  274.32 196.53 270 top
J6  HM4002E-LH  [CN-D2X2-3BRTS0]  295.06 195.64 180 top
J7  RJ45-2X1_M1A-FN-0005  [S-CJ-RJ45-2X1-16SL]  52.85 14.65 0 top
J8  HS5507F-R  [S-CN-S7X2-2HD]  44.83 71.95 270 top
J10  30969-0012D-001  [CJ-RF-D21X7-1]  6 6.69 90 top
J11  30969-0012D-001  [CJ-RF-D21X7-1]  36 6.69 90 top
J12  33019  [CJ-RF-D3_5X3_5-1]  33.8 60.88 180 top
J14  30969-0012D-001  [CJ-RF-D21X7-1]  21 6.69 90 top
J15  33019  [CJ-RF-D3_5X3_5-1]  20.09 60.88 180 top
J17  HC11101  [CN-10X2-2_54]  100.33 147.63 0 top
J19  20438-04321  [CN-S10_16X5_1-4]  71.04 134.71 90 top
J20  20438-04321  [CN-S10_16X5_1-4]  97.76 123.61 90 top
L1  600OHM  [L-0805]  181.34 138.84 270 top
L2  800ohm  [L-S5_5X5-2]  251.71 165.19 90 top
L3  600ohm  [L-0603S0]  194.02 132.61 270 bottom
L4  800ohm  [L-S5_5X5-2]  214.79 83.58 180 bottom
L5  800ohm  [L-S5_5X5-2]  238.35 96.23 90 bottom
L6  800ohm  [L-S5_5X5-2]  225.54 88.38 180 bottom
L7  600ohm  [L-0603S0]  192.88 117.49 0 bottom
L8  800ohm  [L-S5_5X5-2]  195.45 93.27 180 bottom
L9  600ohm  [L-0603S0]  192.75 120.8 180 bottom
L10  600ohm  [L-0603S0]  235.8 120.8 180 bottom
L11  800ohm  [L-S5_5X5-2]  243.26 116.38 180 bottom
L12  600ohm  [L-0603S0]  185.54 105.12 0 bottom
L13  600ohm  [L-0603S0]  193.26 130.45 180 bottom
L14  600ohm  [L-0603S0]  192.59 111.02 180 bottom
L15  600ohm  [L-0603S0]  192.11 136.29 180 bottom
L16  600ohm  [L-0603S0]  190.59 127.91 180 bottom
L17  600ohm  [L-0603S0]  192.59 113.61 0 bottom
L18  600ohm  [L-0603S0]  237.58 115.46 180 bottom
L19  600OHM  [L-0805]  11.32 42.62 180 bottom
L20  600ohm  [L-0603S0]  8.3 28.58 90 bottom
L21  800ohm  [L-S5_5X5-2]  208.56 83.58 180 bottom
L34  1.0uH  [L-S4X4-2L]  148.27 99.68 90 top
L35  1.0uH  [L-S4X4-2L]  140.47 108.26 90 bottom
L36  4.7uH  [L-S3X3]  148.74 104.22 270 top
L37  4.7uH  [L-S3X3]  132.38 107.91 0 bottom
L38  600ohm  [L-0603S0]  118.53 202.77 270 top
L39  39ohm  [L-S3_08X2_9-2]  137.93 86.86 90 bottom
L42  1.0uH  [L-S4X4-2L]  257.96 101.13 0 bottom
L44  39ohm  [L-S3_08X2_9-2]  259.97 88.9 0 bottom
L45  1.0uH  [L-S4X4-2L]  262.99 101.13 0 bottom
L46  1.0uH  [L-S4X4-2L]  281.44 104.86 180 bottom
L47  1.0uH  [L-S4X4-2L]  270.05 107 180 bottom
L48  1uH  [L-S3X3]  290.12 104.36 0 bottom
L49  4.7uH  [L-S4X4-2D-H1_8]  91.21 68.73 90 top
L50  4.7uH  [L-S4X4-2D-H1_8]  97.25 68.73 270 top
L51  4.7uH  [L-S4X4-2D-H1_8]  97.25 68.71 90 bottom
L52  4.7uH  [L-S4X4-2D-H1_8]  91.21 68.71 270 bottom
L53  4.7uH  [L-S4X4-2D-H1_8]  103.29 68.73 90 top
L54  4.7uH  [L-S4X4-2D-H1_8]  109.33 68.73 270 top
L55  4.7uH  [L-S4X4-2D-H1_8]  109.33 68.71 90 bottom
L56  4.7uH  [L-S4X4-2D-H1_8]  103.29 68.71 270 bottom
L57  4.7uH  [L-S4X4-2D-H1_8]  115.36 68.73 90 top
L58  4.7uH  [L-S4X4-2D-H1_8]  121.41 68.73 270 top
L59  4.7uH  [L-S4X4-2D-H1_8]  121.41 68.71 90 bottom
L60  4.7uH  [L-S4X4-2D-H1_8]  115.36 68.71 270 bottom
L61  4.7uH  [L-S4X4-2D-H1_8]  127.44 68.73 90 top
L62  4.7uH  [L-S4X4-2D-H1_8]  133.49 68.73 270 top
L63  4.7uH  [L-S4X4-2D-H1_8]  133.49 68.71 90 bottom
L64  4.7uH  [L-S4X4-2D-H1_8]  127.44 68.71 270 bottom
L65  4.7uH  [L-S4X4-2D-H1_8]  143.38 68.73 90 top
L66  4.7uH  [L-S4X4-2D-H1_8]  149.43 68.73 270 top
L67  4.7uH  [L-S4X4-2D-H1_8]  149.43 68.71 90 bottom
L68  4.7uH  [L-S4X4-2D-H1_8]  143.38 68.71 270 bottom
L69  4.7uH  [L-S4X4-2D-H1_8]  155.46 68.73 90 top
L70  4.7uH  [L-S4X4-2D-H1_8]  161.51 68.73 270 top
L71  4.7uH  [L-S4X4-2D-H1_8]  161.51 68.71 90 bottom
L72  4.7uH  [L-S4X4-2D-H1_8]  155.46 68.71 270 bottom
L73  4.7uH  [L-S4X4-2D-H1_8]  167.54 68.73 90 top
L74  4.7uH  [L-S4X4-2D-H1_8]  173.58 68.73 270 top
L75  4.7uH  [L-S4X4-2D-H1_8]  173.58 68.71 90 bottom
L76  4.7uH  [L-S4X4-2D-H1_8]  167.54 68.71 270 bottom
L77  4.7uH  [L-S4X4-2D-H1_8]  179.62 68.73 90 top
L78  4.7uH  [L-S4X4-2D-H1_8]  185.66 68.73 270 top
L79  4.7uH  [L-S4X4-2D-H1_8]  185.66 68.71 90 bottom
L80  4.7uH  [L-S4X4-2D-H1_8]  179.62 68.71 270 bottom
L81  4.7uH  [L-S4X4-2D-H1_8]  255.88 69.01 90 top
L82  4.7uH  [L-S4X4-2D-H1_8]  261.93 69.01 270 top
L83  4.7uH  [L-S4X4-2D-H1_8]  261.93 69.01 90 bottom
L84  4.7uH  [L-S4X4-2D-H1_8]  255.88 69.01 270 bottom
L85  4.7uH  [L-S4X4-2D-H1_8]  267.96 69.01 90 top
L86  4.7uH  [L-S4X4-2D-H1_8]  274.01 69.01 270 top
L87  4.7uH  [L-S4X4-2D-H1_8]  274.01 69.01 90 bottom
L88  4.7uH  [L-S4X4-2D-H1_8]  267.96 69.01 270 bottom
L89  600ohm  [L-0603S0]  14.35 44.88 0 bottom
L113  4.7uH  [L-S4X4-2D-H1_8]  207.49 68.96 90 top
L114  4.7uH  [L-S4X4-2D-H1_8]  213.53 68.96 270 top
L115  4.7uH  [L-S4X4-2D-H1_8]  213.53 68.96 90 bottom
L116  4.7uH  [L-S4X4-2D-H1_8]  207.49 68.96 270 bottom
L117  4.7uH  [L-S4X4-2D-H1_8]  219.57 68.96 90 top
L118  4.7uH  [L-S4X4-2D-H1_8]  225.61 68.96 270 top
L119  4.7uH  [L-S4X4-2D-H1_8]  225.61 68.96 90 bottom
L120  4.7uH  [L-S4X4-2D-H1_8]  219.57 68.96 270 bottom
L121  4.7uH  [L-S4X4-2D-H1_8]  231.64 68.96 90 top
L122  4.7uH  [L-S4X4-2D-H1_8]  237.69 68.96 270 top
L123  4.7uH  [L-S4X4-2D-H1_8]  237.69 68.96 90 bottom
L124  4.7uH  [L-S4X4-2D-H1_8]  231.64 68.96 270 bottom
L125  4.7uH  [L-S4X4-2D-H1_8]  243.72 68.96 90 top
L126  4.7uH  [L-S4X4-2D-H1_8]  249.77 68.96 270 top
L127  4.7uH  [L-S4X4-2D-H1_8]  249.77 68.96 90 bottom
L128  4.7uH  [L-S4X4-2D-H1_8]  243.72 68.96 270 bottom
L129  1uH  [L-S3X3]  309 78.02 270 top
L130  1uH  [L-S3X3]  295.13 77.61 90 top
L131  1uH  [L-S3X3]  304.38 78.02 270 bottom
L132  1uH  [L-S3X3]  299.75 77.76 270 top
L133  1uH  [L-S3X3]  304.38 78.02 90 top
L134  1uH  [L-S3X3]  299.75 77.76 90 bottom
L135  600ohm  [L-0603S0]  101.79 137.63 0 top
L136  600ohm  [L-0603S0]  108.08 117.91 180 bottom
L137  600ohm  [L-0603S0]  53.41 78.36 0 top
L138  600ohm  [L-0603S0]  91.19 85.27 0 bottom
L139  600ohm  [L-0603S0]  125.38 116.27 0 top
L140  90ohm  [L-2X1_2-4B]  70.85 44.08 90 top
L141  600ohm  [L-0603S0]  113.59 84.84 270 bottom
L159  400ohm  [L-S5_8X5_1-4]  33.99 40.24 270 top
L161  400ohm  [L-S5_8X5_1-4]  27.51 40.24 270 top
L162  400ohm  [L-S5_8X5_1-4]  51.03 45.32 270 top
L163  400ohm  [L-S5_8X5_1-4]  44.35 45.37 270 top
L164  27nH  [L-0603S0]  7.42 25.72 90 bottom
L171  600ohm  [L-0603S0]  145.3 116.64 180 bottom
L172  600ohm  [L-0603S0]  179.2 159.06 180 top
L173  600ohm  [L-0603S0]  134.62 119.31 90 bottom
L174  600ohm  [L-0603S0]  186.25 158.28 90 bottom
L175  600ohm  [L-0603S0]  162.05 83.6 0 top
L176  600ohm  [L-0603S0]  153.72 113.82 0 top
L177  600ohm  [L-0603S0]  166.77 97.59 180 top
L178  4.7uH  [L-S3X3]  28.77 104.04 0 top
L179  4.7uH  [L-S3X3]  4.86 83.13 270 top
L180  4.7uH  [L-S3X3]  7.46 103.32 0 top
L181  4.7uH  [L-S3X3]  8.85 101.9 270 bottom
L182  4.7uH  [L-S3X3]  32.4 99.58 180 bottom
L183  4.7uH  [L-S3X3]  5.43 95.66 90 top
L185  600ohm  [L-0603S0]  39.17 55.7 0 top
L186  1uH  [L-S3X3]  18.01 139.47 270 bottom
L187  600ohm  [L-0603S0]  164.97 125.28 0 bottom
L188  600ohm  [L-0603S0]  149.4 139.5 0 top
L189  600ohm  [L-0603S0]  162.3 131.5 180 bottom
L190  600ohm  [L-0603S0]  162.73 139.44 90 bottom
L191  600ohm  [L-0603S0]  105.46 79.71 0 bottom
L192  600ohm  [L-0603S0]  92.21 193.4 90 bottom
L194  600ohm  [L-0603S0]  57.97 93.67 180 top
L195  600ohm  [L-0603S0]  51.29 105.61 0 bottom
L196  600ohm  [L-0603S0]  57.89 128.72 90 bottom
L197  600ohm  [L-0603S0]  60.56 128.72 270 bottom
L198  600ohm  [L-0603S0]  47.1 106.75 0 top
L199  600ohm  [L-0603S0]  42.52 102.56 0 bottom
L200  600ohm  [L-0603S0]  38.33 107.51 0 bottom
L201  600ohm  [L-0603S0]  38.21 104.59 180 bottom
L203  600ohm  [L-0603S0]  140.97 130.74 180 top
L204  600OHM  [L-0805]  184.91 139.63 270 top
L205  600ohm  [L-0603S0]  191.21 139.65 0 top
L206  600OHM  [L-0805]  183.81 112.26 180 bottom
L207  600ohm  [L-0603S0]  150.11 91.65 0 bottom
L208  600ohm  [L-0603S0]  147.83 84.92 0 bottom
OJ1  0D-FN-0001  [S-CJ-RJ45-D38_7X18_77-28SL]  72.6 16.43 0 top
PC1  100nF  [C-0603S0]  103.6 205.56 0 top
PC2  1uF  [C-0603S0]  102.23 205.56 0 top
PC3  22pF  [C-0402S0]  99.23 209.8 90 top
PC4  22uF  [C-0805]  101.8 211.74 0 top
PC5  330uF  [C-TAN-S7_3X4_3]  121.53 209.1 180 top
PC6  100nF  [C-0603S0]  103.6 211.64 0 top
PC7  4.7uF  [C-0603S0]  118.53 201.37 270 top
PC8  10nF  [C-0402S0]  121.03 190.12 270 bottom
PC9  1uF  [C-0603S0]  83.16 207.73 90 bottom
PC11  1uF  [C-0603S0]  26.04 155.25 270 top
PC12  1uF  [C-0603S0]  302.13 132.9 270 bottom
PC13  1uF  [C-0603S0]  277.15 123.02 270 top
PC14  1uF  [C-0603S0]  26.04 168.97 270 top
PC15  1uF  [C-0603S0]  240.48 194.11 180 top
PC16  1uF  [C-0603S0]  143.43 190.13 270 top
PC17  100nF  [C-0603S0]  81.02 202.21 90 top
PC18  10uF  [C-1206]  81.18 200.3 270 bottom
PC19  10uF  [C-1206]  81.18 200.3 90 top
PC20  1uF  [C-0603S0]  81.02 202.21 270 bottom
PC21  100nF  [C-0603S0]  78.33 211.03 180 top
PC22  100nF  [C-0603S0]  83.16 209.1 90 bottom
PC23  22uF  [C-1210]  75.31 200.03 270 top
PC24  22uF  [C-1210]  75.44 199.52 90 bottom
PC25  22uF  [C-1210]  75.31 196.22 270 top
PC26  1uF  [C-0603S0]  75.31 193.93 90 bottom
PC27  100nF  [C-0603S0]  75.31 193.29 270 top
PC28  8.2nF  [C-0402S0]  84.3 207.3 0 top
PC29  1nF  [C-0603S0]  75.79 203.07 0 bottom
PC30  22pF  [C-0402S0]  81.38 209.56 180 top
PC31  10nF  [C-0603S0]  85.82 204.02 0 top
PC32  100nF  [C-0402S0]  75.18 209.29 270 bottom
PC33  100nF  [C-0402S0]  72.41 211.61 90 top
PC34  1uF  [C-0603S0]  36.7 166.12 0 bottom
PC35  2.2nF  [C-0402S0]  41.78 168.03 270 top
PC36  22uF  [C-1210]  41.91 170.73 90 bottom
PC37  22uF  [C-1210]  41.91 170.73 270 top
PC38  22uF  [C-1210]  41.91 174.54 270 top
PC39  22uF  [C-1210]  41.91 178.35 270 top
PC41  1uF  [C-0603S0]  41.65 167.78 90 bottom
PC42  100nF  [C-0402S0]  41.53 166.43 90 bottom
PC43  150uF/ 3.22A  [CAH-R8-H6_9S0]  50.52 160.35 0 top
PC45  4.7uF  [C-0603S0]  35.77 169.67 180 top
PC46  1nF  [C-0402S0]  28.57 159.77 90 bottom
PC47  100nF  [C-0402S0]  29.99 169.18 270 top
PC48  100uF  [C-1210]  45.73 142.52 90 bottom
PC49  100uF  [C-1210]  45.73 142.52 270 top
PC50  100uF  [C-1210]  45.73 146.51 90 bottom
PC51  100uF  [C-1210]  45.73 146.51 270 top
PC54  1uF  [C-0603S0]  45.7 139.59 270 top
PC55  100nF  [C-0402S0]  297.16 136.75 0 top
PC56  10nF  [S-C-0402]  19.57 151.9 270 top
PC57  330uF  [C-TAN-S7_3X4_3]  38.52 140.8 270 top
PC58  330uF  [C-TAN-S7_3X4_3]  38.61 146.18 270 top
PC60  100nF  [C-0603S0]  34.11 156.43 270 top
PC61  1nF  [C-0603S0]  44.53 161.58 0 top
PC62  100nF  [C-0402S0]  33.54 166.17 180 bottom
PC63  100nF  [C-0402S0]  29.98 150.42 90 bottom
PC64  100nF  [C-0402S0]  33.03 153.59 270 bottom
PC65  100nF  [C-0603S0]  213.13 201.71 90 top
PC66  10uF  [C-1206]  213.41 199.79 270 bottom
PC67  10uF  [C-1206]  213.41 199.79 90 top
PC68  1uF  [C-0603S0]  213.13 201.71 270 bottom
PC69  100nF  [C-0603S0]  210.44 210.45 0 top
PC70  100nF  [C-0603S0]  215.64 206.23 180 bottom
PC71  22uF  [C-0805]  207.36 200.03 270 top
PC72  22uF  [C-0805]  207.47 201.28 90 bottom
PC73  22uF  [C-0805]  207.36 197.49 270 top
PC74  1uF  [C-0805]  207.47 195.07 90 bottom
PC75  100nF  [C-0603S0]  207.47 195.36 270 top
PC76  8.2nF  [C-0402S0]  216.28 206.79 0 top
PC77  1nF  [C-0603S0]  205.49 204.47 0 bottom
PC78  22pF  [C-0402S0]  213.36 209.03 180 top
PC79  10nF  [C-0603S0]  218.31 202.87 0 top
PC82  1nF  [C-0402S0]  285.05 141.78 180 top
PC83  1.5nF  [C-0402S0]  282.38 139.08 90 top
PC84  1nF  [C-0402S0]  291.71 135.3 270 bottom
PC85  33pF  [C-0402S0]  281.3 134.29 180 top
PC86  10pF  [C-0402S0]  283.34 131.5 90 top
PC87  470nF  [C-0402S0]  285.94 130.6 0 bottom
PC88  1nF  [C-0402S0]  281.52 132 180 top
PC89  100nF  [C-0402S0]  45.73 138.28 270 top
PC90  1uF  [C-0603S0]  286.08 129.29 180 top
PC91  2.2uF  [C-0603S0]  287.53 129.32 180 top
PC92  1uF  [C-0603S0]  288.95 129.32 180 top
PC93  1nF  [C-0603S0]  301.97 174.17 270 bottom
PC94  0.1uF  [C-0603S0]  296.29 158.88 90 top
PC95  100nF  [C-0603S0]  306.24 171.73 270 top
PC96  3.3nF  [C-0402S0]  301.72 165.05 90 top
PC97  1uF  [C-0603S0]  301.88 163.84 90 top
PC98  22uF  [C-1210]  302.1 161.62 270 bottom
PC99  22uF  [C-1210]  302.1 160.96 90 top
PC100  22uF  [C-1210]  302.23 166.41 270 bottom
PC101  1nF  [C-0603S0]  301.9 172.13 270 bottom
PC102  2.2uF  [C-0603S0]  297.13 154.41 90 bottom
PC103  150uF  [CAH-R8-H6_9S0]  172.09 196.53 0 top
PC104  2.2uF  [C-0603S0]  296.91 169.87 90 bottom
PC105  470uF  [C-S7_3X4_3-2]  281.19 154.06 0 top
PC109  100uF  [C-1210]  272.69 171.3 180 bottom
PC110  100uF  [C-1210]  272.64 171.3 0 top
PC111  100uF  [C-1210]  276.62 154.92 0 top
PC112  100uF  [C-1210]  276.47 171.3 0 top
PC113  1uF  [C-0603S0]  273.61 161.6 180 top
PC114  100nF  [C-0402S0]  281.31 146.18 180 top
PC115  680pF  [C-0603S0]  297.71 160.77 270 top
PC116  1nF  [C-0603S0]  301.92 158.63 270 bottom
PC117  0.1uF  [C-0603S0]  295.91 174.52 90 top
PC118  3.3nF  [C-0402S0]  301.77 149.24 90 top
PC119  1uF  [C-0603S0]  302.09 148.05 90 top
PC120  22uF  [C-1210]  302.09 145.18 90 top
PC121  22uF  [C-1210]  302.09 145.42 270 bottom
PC122  22uF  [C-1210]  302.21 150.65 270 bottom
PC123  470uF  [C-S7_3X4_3-2]  281.58 154.03 180 bottom
PC125  100nF  [C-0603S0]  305.5 155.86 270 top
PC127  470uF  [C-S7_3X4_3-2]  281.19 169.93 0 top
PC131  100uF  [C-1210]  276.5 161.93 180 top
PC132  100uF  [C-1210]  281.41 161.94 0 bottom
PC133  100uF  [C-1210]  276.5 171.3 180 bottom
PC134  100uF  [C-1210]  281.35 161.93 180 top
PC135  1uF  [C-0603S0]  282.83 146.05 180 top
PC136  100nF  [C-0402S0]  273.92 154.6 0 top
PC137  680pF  [C-0603S0]  297.69 144.78 270 top
PC138  1uF  [C-0603S0]  153.45 191.55 0 bottom
PC139  2.2nF  [C-0402S0]  158.79 192.54 90 bottom
PC140  22uF  [C-1210]  159.04 195.25 90 bottom
PC141  22uF  [C-1210]  159.04 199.06 270 top
PC142  22uF  [C-1210]  159.04 195.25 270 top
PC143  22uF  [C-1210]  159.08 202.87 270 top
PC144  22uF  [C-1210]  159.04 199.06 90 bottom
PC145  1uF  [C-0603S0]  159.17 192.38 270 top
PC146  100nF  [C-0402S0]  158.79 191.52 90 bottom
PC147  4.7uF  [C-0603S0]  151.67 194.47 270 top
PC148  150uF  [CAH-R8-H6_9S0]  295.91 180.27 270 top
PC149  1nF  [C-0402S0]  148.75 182.76 90 bottom
PC150  100nF  [C-0402S0]  147.23 192.44 270 top
PC151  100uF  [C-1210]  177.15 178.87 270 top
PC152  100uF  [C-1210]  177.15 182.68 270 top
PC153  100uF  [C-1210]  177.15 178.87 90 bottom
PC154  100uF  [C-1210]  177.15 182.68 90 bottom
PC155  22uF  [C-1210]  159.08 202.87 90 bottom
PC156  1uF  [C-0603S0]  177.09 173.72 270 top
PC157  100nF  [C-0402S0]  176.96 172.45 270 top
PC158  10nF  [S-C-0402]  176.96 171.43 270 top
PC159  470uF  [C-S7_3X4_3-2]  171.93 170.78 180 top
PC160  470uF  [C-S7_3X4_3-2]  170.74 184.19 0 top
PC162  100nF  [C-0603S0]  153.42 180.61 180 top
PC163  1nF  [C-0603S0]  164.72 187.83 90 top
PC164  100nF  [C-0402S0]  147.23 194.32 270 top
PC165  100nF  [C-0402S0]  147.31 176.41 270 bottom
PC166  100nF  [C-0402S0]  150.96 176.41 270 bottom
PC167  10uF  [C-1206]  191.59 197.53 270 bottom
PC168  10uF  [C-1206]  191.59 197.51 90 top
PC169  10uF  [C-1206]  191.59 200.07 270 bottom
PC170  1uF  [C-0603S0]  191.82 199.51 90 top
PC171  100nF  [C-0603S0]  191.82 200.88 90 top
PC172  100nF  [C-0603S0]  196.85 201.44 270 top
PC173  220nF  [C-0603S0]  195.81 210.99 0 top
PC174  2.2uF  [C-0603S0]  189.76 203.68 180 top
PC175  22uF  [C-0805]  186.64 202.49 90 bottom
PC176  22uF  [C-0805]  186.64 200.46 270 top
PC177  22uF  [C-0805]  186.64 204.52 90 bottom
PC178  22uF  [C-0805]  186.64 204.52 270 top
PC179  22uF  [C-0805]  186.64 202.49 270 top
PC180  1uF  [C-0603S0]  186.69 198.7 90 bottom
PC181  100nF  [C-0603S0]  186.69 198.7 270 top
PC182  1nF  [C-0603S0]  187.58 207.11 0 bottom
PC183  2.7nF  [C-0402S0]  197.4 203.55 180 top
PC184  22nF  [C-0402S0]  196.39 205.33 180 top
PC185  100nF  [C-0402S0]  197.84 198.56 270 top
PC186  100nF  [C-0402S0]  200.38 207.67 270 top
PC187  10uF  [C-1206]  246.43 200.07 270 bottom
PC188  10uF  [C-1206]  246.43 197.53 270 bottom
PC189  10uF  [C-1206]  246.43 197.51 90 top
PC190  1uF  [C-0603S0]  246.66 199.51 90 top
PC191  100nF  [C-0603S0]  246.66 200.88 90 top
PC192  100nF  [C-0603S0]  251.69 201.44 270 top
PC193  220nF  [C-0603S0]  250.65 210.49 0 top
PC194  2.2uF  [C-0603S0]  244.61 203.68 180 top
PC195  22uF  [C-0805]  241.48 201.35 90 bottom
PC196  22uF  [C-0805]  241.48 201.35 270 top
PC197  22uF  [C-0805]  264.95 119.17 0 bottom
PC198  22uF  [C-0805]  228.97 168.41 90 bottom
PC199  22uF  [C-0805]  221.7 167.32 90 bottom
PC200  1uF  [C-0603S0]  241.53 197.56 90 bottom
PC201  100nF  [C-0603S0]  259.43 147.88 180 top
PC202  1nF  [C-0603S0]  242.19 207.14 0 bottom
PC203  1nF  [C-0402S0]  252.24 203.55 180 top
PC204  22nF  [C-0402S0]  251.24 205.33 180 top
PC205  100nF  [C-0402S0]  252.68 198.56 270 top
PC206  100nF  [C-0402S0]  253.72 210.32 180 bottom
PC207  10uF  [C-0805]  261.29 147.88 0 bottom
PC208  10uF  [C-0805]  261.29 147.88 180 top
PC209  100nF  [C-0603S0]  241.53 197.56 270 top
PC210  2.2uF  [C-0603S0]  259.49 153.95 180 top
PC211  100nF  [C-0603S0]  264.54 146.61 90 bottom
PC212  10uF  [C-0805]  264.54 146.64 270 top
PC213  10uF  [C-0805]  264.57 148.98 270 top
PC214  10uF  [C-0805]  264.57 148.98 90 bottom
PC215  1nF  [C-0603S0]  257.94 148.59 0 bottom
PC216  100nF  [C-0603S0]  265.33 154.08 0 bottom
PC217  100nF  [C-0603S0]  263.63 155.07 0 bottom
PC218  10uF  [C-1206]  293.52 117.7 180 top
PC219  10uF  [C-1206]  290.96 117.7 0 bottom
PC220  10uF  [C-1206]  293.5 117.7 0 bottom
PC221  1uF  [C-0603S0]  291.52 117.93 180 top
PC222  100nF  [C-0603S0]  290.14 117.93 180 top
PC223  100nF  [C-0603S0]  289.08 122.95 0 top
PC224  2.2uF  [C-0603S0]  287.35 115.87 270 top
PC225  220nF  [C-0603S0]  280.54 121.91 90 top
PC226  22uF  [C-0805]  288.82 112.74 0 top
PC227  22uF  [C-0805]  286.89 112.74 180 bottom
PC228  22uF  [C-0805]  286.89 112.74 0 top
PC229  22uF  [C-0805]  290.75 112.74 0 top
PC230  22uF  [C-0805]  290.75 112.74 180 bottom
PC231  1uF  [C-0603S0]  292.52 112.67 180 bottom
PC232  100nF  [C-0603S0]  292.52 112.67 0 top
PC233  1nF  [C-0603S0]  286.97 115.97 90 bottom
PC234  1nF  [C-0402S0]  287.48 123.5 270 top
PC235  22nF  [C-0402S0]  285.7 122.5 270 top
PC236  100nF  [C-0402S0]  292.47 123.95 0 top
PC237  100nF  [C-0402S0]  280.8 124.47 0 top
PC238  100nF  [C-0603S0]  231.23 201.45 90 top
PC239  10uF  [C-1206]  231.51 199.54 90 top
PC240  10uF  [C-1206]  231.51 199.54 270 bottom
PC241  1uF  [C-0603S0]  231.23 201.45 270 bottom
PC242  100nF  [C-0603S0]  228.54 210.53 180 top
PC243  100nF  [C-0603S0]  232.21 208.52 90 bottom
PC244  22uF  [C-0805]  225.46 199.73 270 top
PC245  22uF  [C-0805]  225.46 197.19 270 top
PC246  22uF  [C-0805]  225.46 199.75 90 bottom
PC247  1uF  [C-0603S0]  225.57 195.08 90 bottom
PC248  100nF  [C-0603S0]  225.57 195.1 270 top
PC249  8.2nF  [C-0402S0]  234.38 206.54 0 top
PC250  1nF  [C-0603S0]  225.87 202.29 0 bottom
PC251  22pF  [C-0402S0]  231.46 208.77 180 top
PC252  10nF  [C-0603S0]  235.88 203.26 0 top
PC300  4.7uF  [C-0603S0]  61.34 210.31 0 top
PC307  470uF  [C-S7_3X4_3-2]  281.16 169.91 180 bottom
PC309  100nF  [C-0402S0]  225.59 210.64 270 top
PC310  100nF  [C-0402S0]  226.24 207.44 180 bottom
PC311  1uF  [C-0603S0]  273.93 123.02 270 top
PC313  330uF  [C-TAN-S7_3X4_3]  110.87 209.1 180 top
PC314  330uF  [C-TAN-S7_3X4_3]  116.2 209.1 180 top
PC315  10uF  [C-1206]  63.92 198.75 90 bottom
PC316  10uF  [C-1206]  63.9 198.75 270 top
PC317  1uF  [C-0603S0]  62.33 195.35 0 bottom
PC318  100nF  [C-0402S0]  64.11 196.75 90 bottom
PC319  1uF  [C-0603S0]  62.33 192.7 180 bottom
PC320  100nF  [C-0402S0]  65.15 188.67 90 bottom
PC321  22uF  [C-0805]  64.99 191.89 90 bottom
PC322  22uF  [C-0805]  64.98 189.69 270 top
PC323  22uF  [C-0805]  64.98 187.74 270 top
PC324  100nF  [C-0402S0]  58.07 192.74 180 top
PC325  100nF  [C-0402S0]  60.36 191.01 0 top
PC326  10nF  [C-0402S0]  66.05 143.23 270 top
PC327  100nF  [C-0402S0]  66.05 144.22 270 top
PC328  10uF  [C-0805-H1_35]  66.25 145.77 270 top
PC329  10uF  [C-0805-H1_35]  66.25 147.7 270 top
PC330  22uF  [C-0805]  50.04 118.62 90 bottom
PC331  22uF  [C-0805]  36.43 121.36 0 bottom
PC332  22uF  [C-0805]  36.43 112.85 180 bottom
PC333  1uF  [C-0603S0]  57.76 137.59 270 top
PC334  100nF  [C-0402S0]  57.61 136.34 270 top
PC335  1nF  [C-0603S0]  61.25 141.98 0 top
PC336  10nF  [C-0402S0]  82.07 143.23 270 top
PC337  100nF  [C-0402S0]  82.07 144.22 270 top
PC338  10uF  [C-0805-H1_35]  82.27 147.7 270 top
PC339  10uF  [C-0805-H1_35]  82.27 145.77 270 top
PC340  22uF  [C-0805]  73.89 145.36 90 bottom
PC341  22uF  [C-0805]  60.32 112.02 90 bottom
PC342  22uF  [C-0805]  73.89 143.26 90 bottom
PC343  1uF  [C-0603S0]  73.79 141.99 270 top
PC344  100nF  [C-0402S0]  62.59 126.69 90 top
PC345  1nF  [C-0603S0]  77.27 141.98 0 top
PC364  1uF  [C-0603S0]  290.89 133.24 270 bottom
PC365  1nF  [C-0603S0]  301.8 156.35 270 bottom
PC366  100nF  [C-0402S0]  207.95 209.54 270 bottom
PC367  100nF  [C-0402S0]  204.39 211.66 90 top
